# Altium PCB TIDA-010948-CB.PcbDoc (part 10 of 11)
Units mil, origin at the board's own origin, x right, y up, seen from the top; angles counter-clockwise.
Board outline 8100 x 8400 mil, 8 copper layers (L01 - TOP, L02 - GND, L03 - SIG, L04 - GND, L05 - PWR, L06 - SIG, L07 - GND, L08 - BOTTOM), stack 59.656 mil thick; 711 components, 572 nets, 2646 pads, 1325 vias.
Unrouted connection lines stored in the file: 988.
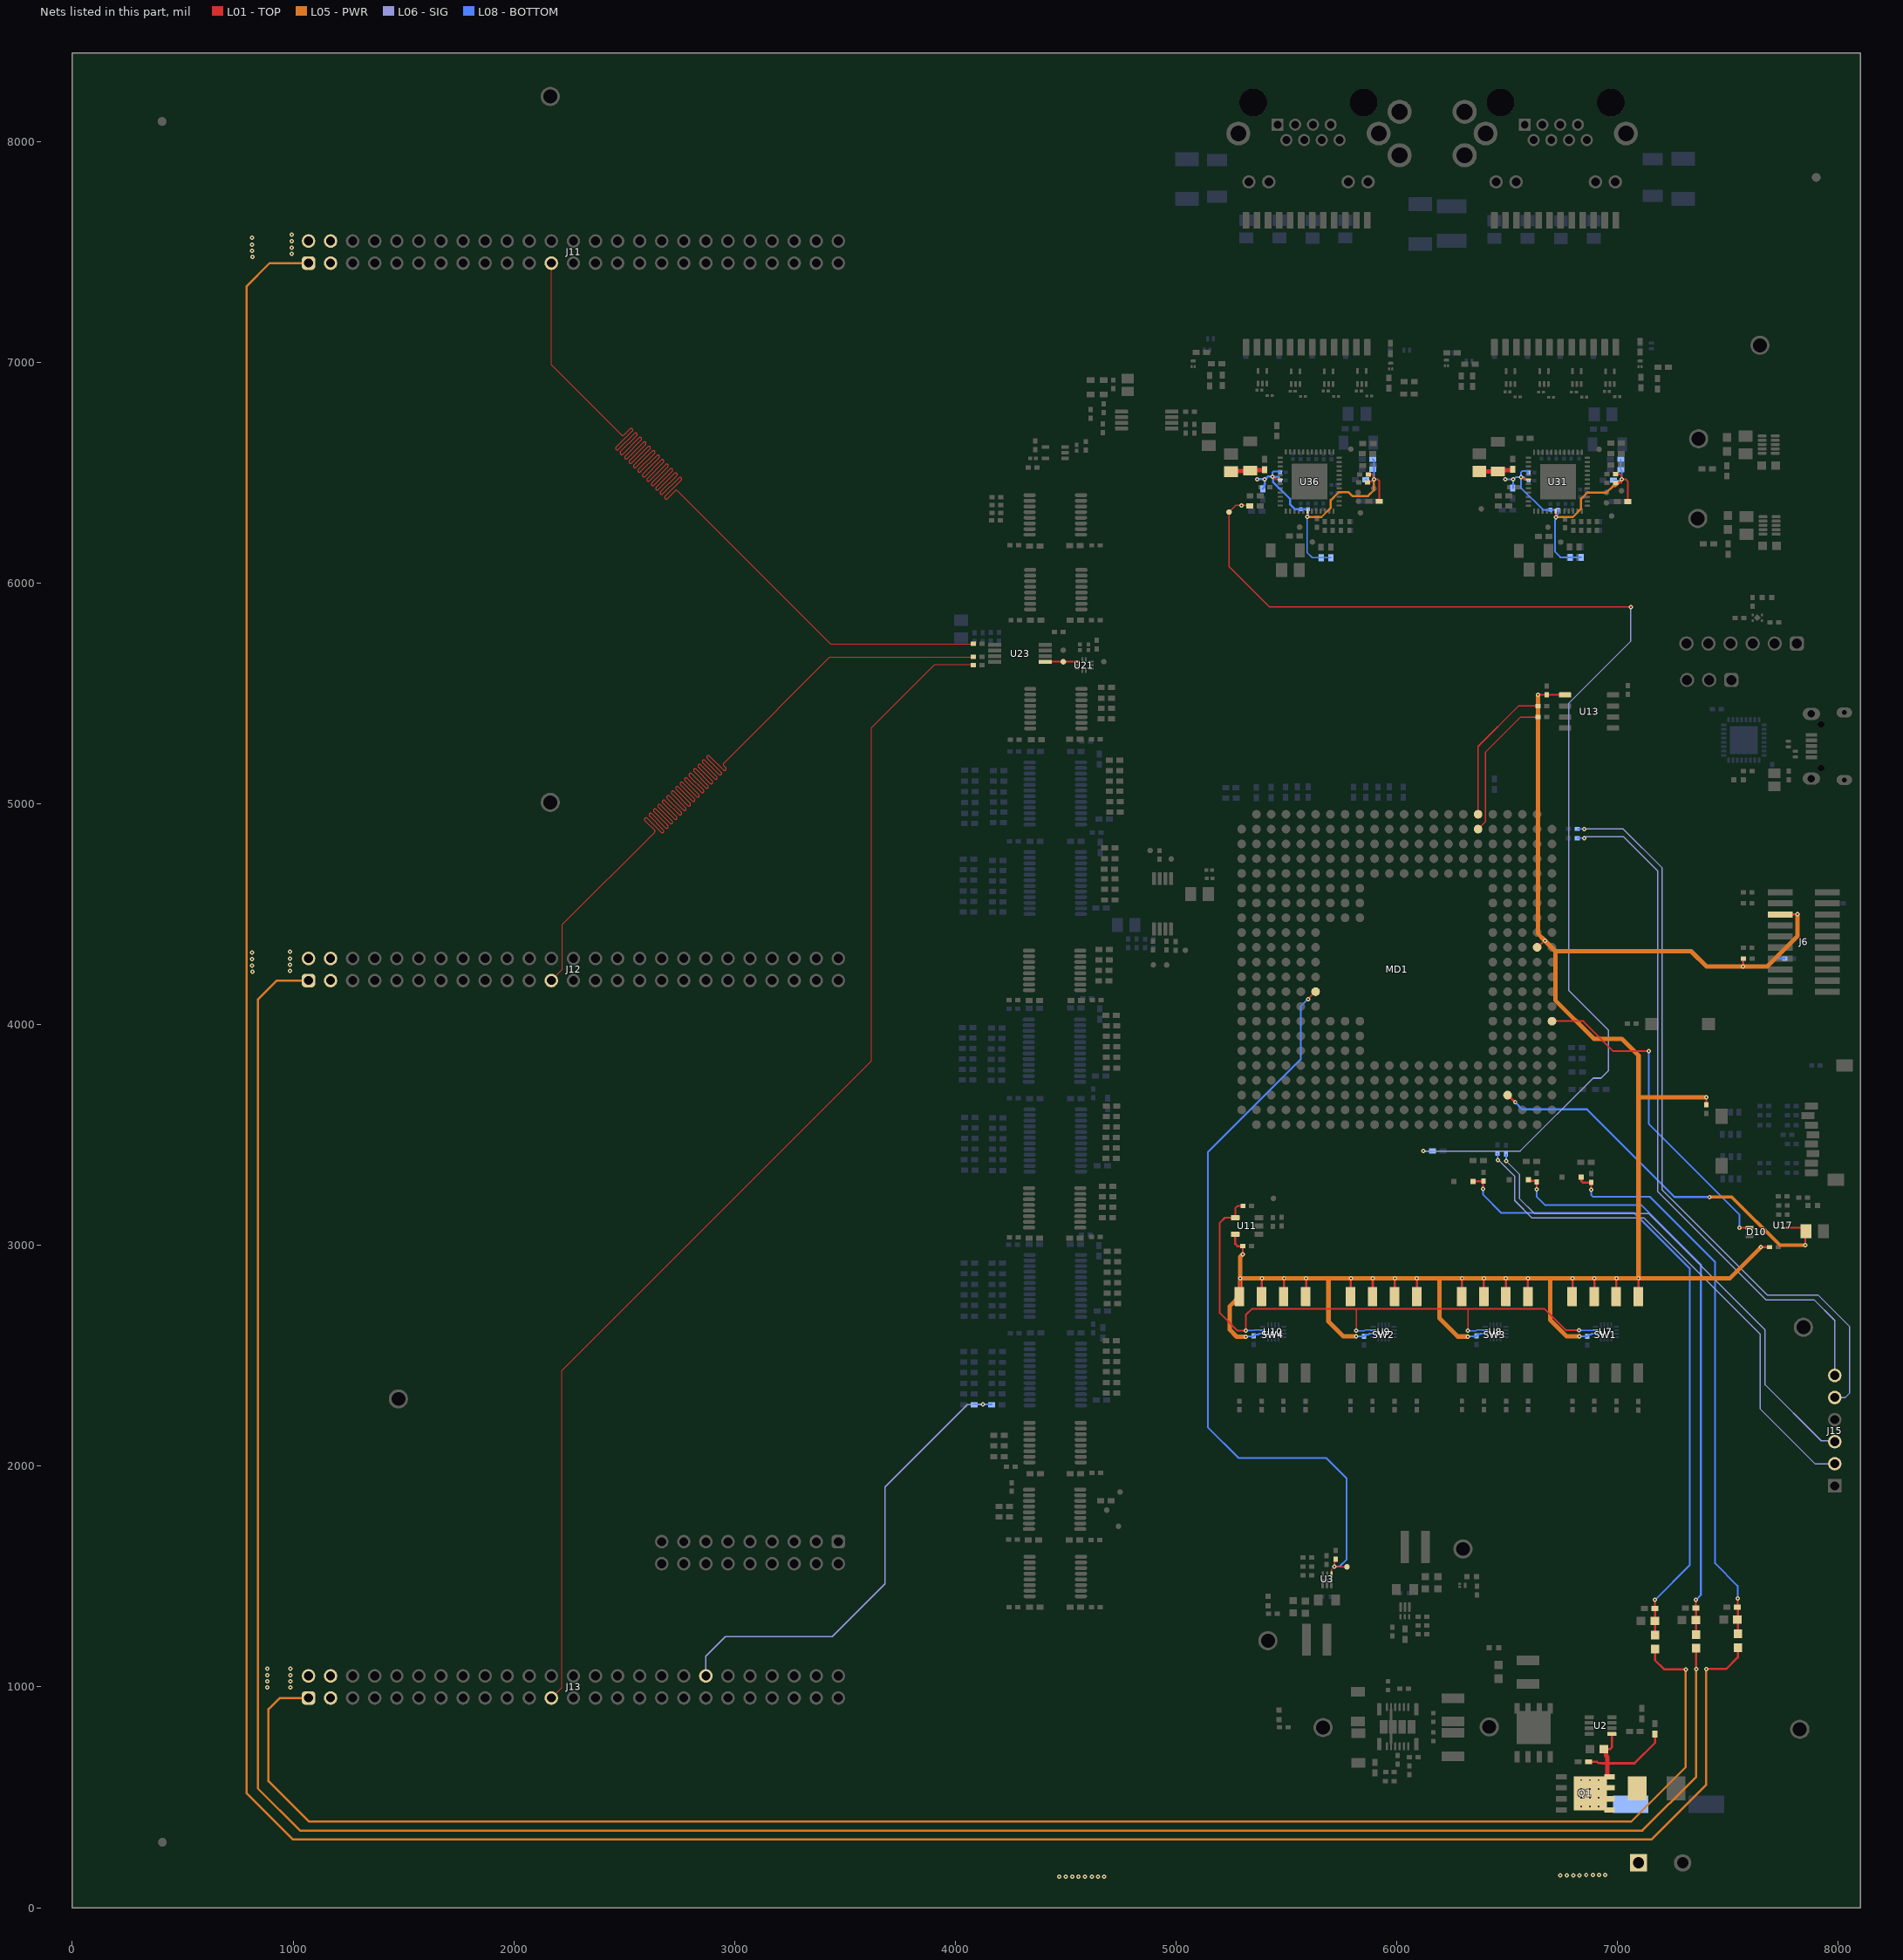
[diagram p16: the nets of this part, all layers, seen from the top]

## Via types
v1: diameter 19.68, hole 7.87, L01 - TOP to L08 - BOTTOM, 1310 vias
v2: diameter 20, hole 7.87, L01 - TOP to L08 - BOTTOM, tented both sides, 7 vias
v3: diameter 200, hole 144, L01 - TOP to L08 - BOTTOM, 6 vias
v4: diameter 20, hole 8, L01 - TOP to L08 - BOTTOM, tented both sides, 2 vias

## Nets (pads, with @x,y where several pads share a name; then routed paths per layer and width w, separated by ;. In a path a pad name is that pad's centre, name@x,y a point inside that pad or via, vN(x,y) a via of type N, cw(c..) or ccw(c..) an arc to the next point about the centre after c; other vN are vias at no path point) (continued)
PWMC6L: C102.1 J13.38 R206.2 | length 2154.7
  L06 - SIG w5.25: J13.38@2870,1050 2870,1140 2957.75,1227.75 3442.25,1227.75 3680.5,1466 3680.5,1905.36 4054.64,2279.5 v1(4125.5,2279.5)
  L08 - BOTTOM w8: C102.1@4084.78,2279.5 v1(4125.5,2279.5) 4126,2279 R206.2@4164.38,2279
RESETSTATz: D10.1 MD1.R22 | length 1511.6
  L01 - TOP w8: MD1.R22@6702.76,4015.35 6844.15,4015.35 6979,3880.5 v1(7141,3880.5) ; v1(7552,3080) 7552.34,3080.34 7598.16,3080.34 D10.1@7598.5,3080.69
  L08 - BOTTOM w8: v1(7141,3880.5) 7141,3551 7552,3140 v1(7552,3080)
SBC1: J15.2 R310.2 | length 2391.2
  L06 - SIG w6: v1(6457,3385.5) 6461.5,3385.5 6534,3313 6534,3203 6613.21,3123.79 7120.5,3123.79 7645.5,2598.79 7645.5,2260 7894.5,2011 J15.2@7984,2011
  L08 - BOTTOM w6: R310.2@6455.5,3416.81 6457,3415.31 v1(6457,3385.5)
SBC2: J15.6 R307.1 | length 3172.9
  L06 - SIG w6: v1@6848.5,4850.5 7027,4850.5 7181,4696.5 7181,3244.5 7672,2753.5 7890.5,2753.5 7984,2660 J15.6@7984,2411
  L08 - BOTTOM w6: R307.1@6818.19,4844 6818.69,4844.5 v1(6848.5,4844.5)
SDM_CLK_AX12: J11.23 R111.2 | length 5579
  L01 - TOP w4.25: J11.23@2170,7449.2 2170,6989 2474,6685 2488.69,6670.31 ccw(c2493.73,6675.35) 2498.76,6670.31 2526.59,6698.14 cw(c2531.62,6693.1) 2536.66,6698.14 cw(c2531.62,6693.1) 2536.66,6688.06 2463.17,6614.57 ccw(c2468.21,6609.53) 2463.17,6604.49 ccw(c2468.21,6609.53) 2473.25,6604.49 2546.74,6677.98 cw(c2551.78,6672.95) 2556.82,6677.98 cw(c2551.78,6672.95) 2556.82,6667.91 2483.32,6594.42 ccw(c2488.36,6589.38) 2483.32,6584.34 ccw(c2488.36,6589.38) 2493.4,6584.34 2566.89,6657.83 cw(c2571.93,6652.79) 2576.97,6657.83 cw(c2571.93,6652.79) 2576.97,6647.75 2503.48,6574.26 ccw(c2508.52,6569.23) 2503.48,6564.19 ccw(c2508.52,6569.23) 2513.55,6564.19 2587.04,6637.68 cw(c2592.08,6632.64) 2597.12,6637.68 cw(c2592.08,6632.64) 2597.12,6627.6 2523.63,6554.11 ccw(c2528.67,6549.07) 2523.63,6544.04 ccw(c2528.67,6549.07) 2533.71,6544.04 2607.2,6617.53 cw(c2612.23,6612.49) 2617.27,6617.53 cw(c2612.23,6612.49) 2617.27,6607.45 2543.78,6533.96 ccw(c2548.82,6528.92) 2543.78,6523.88 ccw(c2548.82,6528.92) 2553.86,6523.88 2627.35,6597.37 cw(c2632.39,6592.33) 2637.43,6597.37 cw(c2632.39,6592.34) 2637.43,6587.3 2563.93,6513.81 ccw(c2568.97,6508.77) 2563.93,6503.73 ccw(c2568.97,6508.77) 2574.01,6503.73 2647.5,6577.22 cw(c2652.54,6572.18) 2657.58,6577.22 cw(c2652.54,6572.18) 2657.58,6567.14 2584.09,6493.65 ccw(c2589.13,6488.62) 2584.09,6483.58 ccw(c2589.13,6488.62) 2594.16,6483.58 2667.65,6557.07 cw(c2672.69,6552.03) 2677.73,6557.07 cw(c2672.69,6552.03) 2677.73,6546.99 2604.24,6473.5 ccw(c2609.28,6468.46) 2604.24,6463.42 ccw(c2609.28,6468.46) 2614.32,6463.42 2687.81,6536.92 cw(c2692.84,6531.88) 2697.88,6536.92 cw(c2692.84,6531.88) 2697.88,6526.84 2624.39,6453.35 ccw(c2629.43,6448.31) 2624.39,6443.27 ccw(c2629.43,6448.31) 2634.47,6443.27 2707.96,6516.76 cw(c2713,6511.72) 2718.04,6516.76 cw(c2713,6511.72) 2718.04,6506.69 2644.54,6433.2 ccw(c2649.58,6428.16) 2644.54,6423.12 ccw(c2649.58,6428.16) 2654.62,6423.12 2728.11,6496.61 cw(c2733.15,6491.57) 2738.19,6496.61 cw(c2733.15,6491.57) 2738.19,6486.53 2664.7,6413.04 ccw(c2669.74,6408.01) 2664.7,6402.97 ccw(c2669.74,6408.01) 2674.77,6402.97 2748.26,6476.46 cw(c2753.3,6471.42) 2758.34,6476.46 cw(c2753.3,6471.42) 2758.34,6466.38 2684.85,6392.89 ccw(c2689.89,6387.85) 2684.85,6382.81 ccw(c2689.89,6387.85) 2694.93,6382.81 2730.52,6418.41 cw(c2735.56,6413.37) 2740.59,6418.41 2742.1,6416.9 3434,5725 R111.2@4081.81,5725
SDM_CLK_AX34: J12.23 R112.2 | length 5578.3
  L01 - TOP w4.25: J12.23@2170,4199.6 2220,4249.6 2220,4453.59 2635.92,4869.5 2637.42,4871.01 ccw(c2632.38,4876.05) 2637.42,4881.08 2593.78,4924.72 cw(c2598.82,4929.76) 2593.78,4934.8 cw(c2598.82,4929.76) 2603.86,4934.8 2667.53,4871.13 ccw(c2672.57,4876.16) 2677.61,4871.13 ccw(c2672.57,4876.16) 2677.61,4881.2 2613.94,4944.87 cw(c2618.97,4949.91) 2613.94,4954.95 cw(c2618.97,4949.91) 2624.01,4954.95 2687.68,4891.28 ccw(c2692.72,4896.32) 2697.76,4891.28 ccw(c2692.72,4896.32) 2697.76,4901.35 2634.09,4965.03 cw(c2639.13,4970.06) 2634.09,4975.1 cw(c2639.13,4970.06) 2644.16,4975.1 2707.84,4911.43 ccw(c2712.87,4916.47) 2717.91,4911.43 ccw(c2712.87,4916.47) 2717.91,4921.51 2654.24,4985.18 cw(c2659.28,4990.22) 2654.24,4995.25 cw(c2659.28,4990.22) 2664.32,4995.25 2727.99,4931.58 ccw(c2733.03,4936.62) 2738.06,4931.58 ccw(c2733.03,4936.62) 2738.06,4941.66 2674.39,5005.33 cw(c2679.43,5010.37) 2674.39,5015.41 cw(c2679.43,5010.37) 2684.47,5015.41 2748.14,4951.74 ccw(c2753.18,4956.77) 2758.22,4951.74 ccw(c2753.18,4956.77) 2758.22,4961.81 2694.55,5025.48 cw(c2699.58,5030.52) 2694.55,5035.56 cw(c2699.58,5030.52) 2704.62,5035.56 2768.29,4971.89 ccw(c2773.33,4976.93) 2778.37,4971.89 ccw(c2773.33,4976.93) 2778.37,4981.96 2714.7,5045.64 cw(c2719.74,5050.67) 2714.7,5055.71 cw(c2719.74,5050.67) 2724.77,5055.71 2788.45,4992.04 ccw(c2793.48,4997.08) 2798.52,4992.04 ccw(c2793.48,4997.08) 2798.52,5002.12 2734.85,5065.79 cw(c2739.89,5070.83) 2734.85,5075.86 cw(c2739.89,5070.83) 2744.93,5075.86 2808.6,5012.19 ccw(c2813.64,5017.23) 2818.67,5012.19 ccw(c2813.64,5017.23) 2818.67,5022.27 2755,5085.94 cw(c2760.04,5090.98) 2755,5096.02 cw(c2760.04,5090.98) 2765.08,5096.02 2828.75,5032.35 ccw(c2833.79,5037.38) 2838.83,5032.35 ccw(c2833.79,5037.38) 2838.83,5042.42 2775.16,5106.09 cw(c2780.19,5111.13) 2775.16,5116.17 cw(c2780.19,5111.13) 2785.23,5116.17 2848.9,5052.5 ccw(c2853.94,5057.54) 2858.98,5052.5 ccw(c2853.94,5057.54) 2858.98,5062.57 2795.31,5126.25 cw(c2800.35,5131.28) 2795.31,5136.32 cw(c2800.35,5131.28) 2805.38,5136.32 2869.06,5072.65 ccw(c2874.09,5077.69) 2879.13,5072.65 ccw(c2874.09,5077.69) 2879.13,5082.73 2815.46,5146.4 cw(c2820.5,5151.44) 2815.46,5156.48 cw(c2820.5,5151.44) 2825.54,5156.48 2889.21,5092.8 ccw(c2894.25,5097.84) 2899.28,5092.8 ccw(c2894.25,5097.84) 2899.28,5102.88 2835.61,5166.55 cw(c2840.65,5171.59) 2835.61,5176.63 cw(c2840.65,5171.59) 2845.69,5176.63 2909.36,5112.96 ccw(c2914.4,5117.99) 2919.44,5112.96 ccw(c2914.4,5117.99) 2919.44,5123.03 2855.77,5186.7 cw(c2860.8,5191.74) 2855.77,5196.78 cw(c2860.8,5191.74) 2865.84,5196.78 2929.51,5133.11 ccw(c2934.55,5138.15) 2939.59,5133.11 ccw(c2934.55,5138.15) 2939.59,5143.18 2875.92,5206.86 cw(c2880.96,5211.89) 2875.92,5216.93 cw(c2880.96,5211.89) 2885.99,5216.93 2949.67,5153.26 ccw(c2954.7,5158.3) 2959.74,5153.26 ccw(c2954.7,5158.3) 2959.74,5163.34 2949.78,5173.3 cw(c2954.82,5178.33) 2949.78,5183.37 2963.91,5197.5 3430.41,5664 4080.81,5664 R112.2@4082.31,5665.5
SDM_CLK_AX56: J13.23 R110.2 | length 5576.2
  L01 - TOP w4.25: J13.23@2170,950 2217.5,997.5 2217.5,2433 3621,3836.5 3621,5345.5 3906,5630.5 4079.81,5630.5 R110.2@4081.81,5628.5
SDM_CLK_SOURCE: TP23.1 U21.8 U23.1 | length 144.3
  L01 - TOP w6: U23.1@4407.17,5643.11 U23.1@4407.41,5643.35 ; TP23.1@4488.77,5643.35 TP23.1@4489,5643.58 TP23.1@4489.15,5643.73 ; U21.8@4551,5643.73 U21.8@4551.15,5643.88
  L01 - TOP w8: U23.1@4407.41,5643.35 TP23.1@4488.77,5643.35 ; TP23.1@4489.15,5643.73 U21.8@4551,5643.73
STO1: J15.3 R309.2 | length 2256.4
  L06 - SIG w6: v1(6495.5,3382) 6555,3322.5 6555,3212.5 6623.5,3144 7141,3144 7668.5,2616.5 7668.5,2368.5 7922.5,2114.5 7980.5,2114.5 J15.3@7984,2111
  L08 - BOTTOM w6: R309.2@6494.5,3413.31 6495.5,3412.31 v1(6495.5,3382)
STO2: J15.5 R306.1 | length 3398.1
  L06 - SIG w6: v1(6848.5,4886) 7026,4886 7202.5,4709.5 7202.5,3250.5 7677.5,2775.5 7908,2775.5 8050.5,2633 8050.5,2329.5 8032,2311 J15.5@7984,2311
  L08 - BOTTOM w6: R306.1@6818.19,4886.5 6818.69,4886 v1(6848.5,4886)
Switch_Bootcfg: R60.2 U7.15 U8.15 U9.15 U10.15 U11.4 | length 2864.9
  L01 - TOP w6: v1(5816,2613) 5816,2713 ; v1(6322,2613) 6322,2713
  L01 - TOP w8: R60.2@5303.31,3179 5279,3179 5267.87,3167.87 U11.4@5267.87,3125.4 5221.4,3125.4 5198,3102 5198,2693 5277.22,2613.78 v1(5316,2613.78) 5316,2685 5344,2713 5816,2713 6322,2713 6669,2713 6767,2615 v1(6825,2615)
  L08 - BOTTOM w6: v1(5316,2613.78) 5352.55,2613.78 5354.65,2615.87 U10.15@5392.76,2615.87 ; v1(5816,2613) 5852.66,2613 5855.54,2615.87 U9.15@5893.76,2615.87 ; v1(6322,2613) 6358.66,2613 6361.54,2615.87 U8.15@6399.76,2615.87 ; v1(6825,2615) 6825.44,2615.44 6899.32,2615.44 U7.15@6899.76,2615.87
SYSCLKOUT0: R220.1 R260.1 TP13.1 | length 5574.7
  L01 - TOP w6: R260.1@5333.88,6349 5331.38,6351.5 v1(5295.5,6351.5) 5270,6351.5 TP13.1@5240,6321.5 5240,6074.5 5422.56,5891.94 v1(7060,5891.94)
  L06 - SIG w6: v1(6120,3427.5) 6559.15,3427.5 6889.15,3757.5 6925,3757.5 6959.5,3792 6959.5,3974 6778.32,4155.18 6778.32,5454.81 7060,5736.49 v1(7060,5891.94) v1@7060,5893
  L08 - BOTTOM w6: v1(6120,3427.5) 6160.88,3427.5 R220.1@6161.38,3427
TQMaX4XxL_PGOOD: MD1.N6 R19.2 TP22.1 U3.1 | length 3465.8
  L01 - TOP w6: U3.1@5703.69,1511.59 5703.69,1530.68 v1(5718,1545) ; R19.2@5723,1578.31 5718,1573.31 v1(5718,1545) ; TP22.1@5774,1544 5773.5,1544.5 5718.5,1544.5 v1(5718,1545)
  L01 - TOP w8: v1(5598,4116) 5598.34,4116 5631.55,4149.21 MD1.N6@5631.89,4149.21
  L08 - BOTTOM w8: v1(5598,4116) 5565.78,4083.78 5565.78,3844.28 5145,3423.5 5145,3388.65 5145,2175 5283,2037 5680,2037 5773,1944 5773,1578 5740,1545 v1(5718,1545)
UART0_RXD: MD1.A17 R61.1 | length 655.7
  L01 - TOP w6: MD1.A17@6368.11,4952.36 6368.11,5260.11 6551,5443 R61.1@6640.31,5443
UART0_TXD: MD1.B17 R63.1 | length 666.8
  L01 - TOP w6: MD1.B17@6368.11,4885.43 6401,4918.32 6401,5233 6561,5393 R63.1@6640.31,5393
V_1V8_MOD: C28.1 C30.1 C31.1 C32.1 C33.1 C35.1 J6.5 MD1.K21 R82.2 R86.2 R87.2 R88.2 SW1.5 SW1.6 SW1.7 SW1.8 SW2.5 SW2.6 SW2.7 SW2.8 SW3.5 SW3.6 SW3.7 SW3.8 SW4.5 SW4.6 SW4.7 SW4.8 U7.14 U8.14 U9.14 U10.14 U11.5 U13.1 | length 10728.1
  L01 - TOP w8: v1(5301.5,2959.5) 5301.91,2959.91 5301.91,2995.59 C28.1@5302.31,2996 ; v1(6639,5493) 6639.66,5493.66 6679.34,5493.66 C35.1@6680,5494.31 6680.66,5493.66 6762.07,5493.66 U13.1@6762.73,5493 ; R82.2@7402.83,3636.51 7402.91,3636.6 7402.91,3670.41 v1(7403,3670.5) ; v1(7650,2992) R88.2@7688.31,2992
  L01 - TOP w10: U11.5@5267.87,3050.6 5267.87,3006.13 5278,2996 C28.1@5302.31,2996 ; SW4.8@5287,2769.23 5290,2772.23 v1(5290,2850) v1@5290,2851 ; SW4.7@5387,2769.23 5389,2771.23 v1(5389,2850) ; SW4.6@5487,2769.23 5489,2771.23 v1(5489,2850) ; SW4.5@5587,2769.23 5589,2771.23 v1(5589,2850) ; SW2.8@5790,2769.23 5792,2771.23 v1(5792,2850) ; SW2.7@5890,2769.23 5891,2770.23 v1(5891,2850) ; SW2.6@5990,2769.23 5991,2770.23 v1(5991,2850) ; SW2.5@6090,2769.23 6091,2770.23 v1(6091,2850) ; SW3.8@6294,2769.23 6295,2770.23 v1(6295,2850) ; SW3.7@6394,2769.23 v1(6394,2850) ; SW3.6@6494,2769.23 v1(6494,2850) ; SW3.5@6594,2769.23 v1(6594,2850) ; MD1.K21@6635.83,4349.99 6638.41,4349.99 6668.42,4380 v1(6671,4380) ; SW1.8@6794,2768.23 6796,2770.23 v1(6796,2850) ; SW1.7@6894,2768.23 6895,2769.23 v1(6895,2850) ; SW1.6@6994,2768.23 6995,2769.23 v1(6995,2850) ; SW1.5@7094,2768.23 7095,2769.23 v1(7095,2850) ; v1(7569,4263) 7569.66,4263.66 7569.66,4298.34 R86.2@7570.31,4299 ; J6.5@7737.5,4499 7738,4499.5 7814.5,4499.5 v1(7815,4500)
  L05 - PWR w8: 7095,3670.73 7097.27,3673
  L05 - PWR w20: v1(5301.5,2959.5) 5290,2948 v1(5290,2850) ; v1(5316,2586) 5275,2586 5243.62,2617.38 5243.62,2725 5290,2771.38 v1(5290,2850) ; v1(5816,2588) 5757.42,2588 5690.5,2654.92 5690.5,2850 ; v1(6322,2587) 6276.48,2587 6193,2670.48 6193,2850 ; v1(6639,5493) 6639,4412 v1(6671,4380) 6718.5,4332.5 7333.5,4332.5 7403,4263 v1(7569,4263) 7678,4263 7815,4400 v1(7815,4500) ; 6718.24,4332.76 6718.24,4110.26 6893.1,3935.4 7019.6,3935.4 7095,3860 7095,3670.73 ; v1(6828,2588) 6769.5,2588 6695,2662.5 6695,2850 ; v1(7403,3670.5) 7402.77,3670.73 7095,3670.73 ; v1(7650,2992) 7508,2850 v1(7095,2850) ; v1(5290,2850) v1(5389,2850) v1(5489,2850) v1(5589,2850) 5690.5,2850 ; 5690.5,2850 v1(5792,2850) v1(5891,2850) v1(5991,2850) v1(6091,2850) 6193,2850 ; 6193,2850 v1(6295,2850) v1(6394,2850) v1(6494,2850) v1(6594,2850) 6695,2850 ; 6695,2850 v1(6796,2850) v1(6895,2850) v1(6995,2850) v1(7095,2850) ; v1(7095,2850) 7095,3670.73
  L08 - BOTTOM w8: v1(5316,2586) 5317.84,2587.84 5350.16,2587.84 C33.1@5352,2589.68 5352,2590.16 5357.84,2596 5373,2596 5377.06,2600.06 5392.69,2600.06 U10.14@5392.76,2600.13 ; v1(5816,2588) 5816.16,2587.84 5851.84,2587.84 C32.1@5852,2587.68 5852,2589.65 5857.84,2595.5 5872.5,2595.5 5877.06,2600.06 5893.69,2600.06 U9.14@5893.76,2600.13 ; v1(6322,2587) 6323.84,2588.84 6360.16,2588.84 C31.1@6362,2590.68 6362,2592.16 6367.84,2598 6378,2598 6380.13,2600.13 U8.14@6399.76,2600.13 ; v1(6828,2588) 6828.16,2587.84 6861.84,2587.84 C30.1@6862,2587.68 ; C30.1@6862,2589.65 6867.84,2595.5 6879.5,2595.5 6884.06,2600.06 6899.69,2600.06 U7.14@6899.76,2600.13
  L08 - BOTTOM w10: v1(7569,4263) 7681,4263 7717,4299 R87.2@7757.31,4299
V_VDDSHV5_SD: C46.1 MD1.Y19 U17.A2 U17.B2 | length 1805.8
  L01 - TOP w8: U17.B2@7749,3080.16 U17.A2@7768.69,3080.16 7836.84,3080.16 C46.1@7853,3064 7851,3062 v1(7851,3000.5)
  L01 - TOP w10: MD1.Y19@6501.97,3680.7 6502.63,3680.7 6535.34,3648 v1(6536,3648)
  L05 - PWR w15: v1(7417,3219) 7517.28,3219 7735.78,3000.5 v1(7851,3000.5)
  L08 - BOTTOM w10: v1(6536,3648) 6568,3616 6862,3616 7259,3219 v1(7417,3219)
VBUS: C3.1 C11.1 D3.2 J1.1 J11.1 J11.2 J11.3 J11.4 J12.1 J12.2 J12.3 J12.4 J13.1 J13.2 J13.3 J13.4 Q1.5 Q1.6 Q1.7 Q1.8 Q1.9 R9.2 R11.2 R311.2 R312.2 R313.2 U2.5 | length 34201.3
  L01 - TOP w10: R9.2@6868.62,661 6906.62,661 6913.43,654.19 6926.81,654.19 6927,654 6954,654 7077,654 7170,747 R11.2@7170,786.38 ; C11.1@6937.5,719 6938.48,719 6967.02,719 6974.18,726.16 U2.5@6974.18,786.61 ; R311.2@7169.86,1171.41 7169.86,1121.14 7212,1079 v1(7308.5,1079) ; R312.2@7355.17,1174.69 7356.55,1173.31 v1(7356.55,1081.61) ; v1(7401.5,1081) 7492,1081 7544.62,1133.62 R313.2@7544.62,1178.24
  L01 - TOP w20: C11.1@6938.48,719 6947.18,710.3 6947.18,688.82 6954,682 6954,654 6954,595 6956,593 Q1.8@6964,593
  L05 - PWR w10: J13.1@1070,950 940,950 889,899 889,573 1072,390 7061.5,390 7308.5,637 v1(7308.5,1079) ; J12.1@1070,4199.6 926.1,4199.6 840,4113.5 840,540.5 1031.5,349 7112,349 7356.55,593.55 v1(7356.55,1081.61) ; J11.1@1070,7449.2 894.2,7449.2 788.5,7343.5 788.5,519 999,308.5 7152.5,308.5 7401.5,557.5 v1(7401.5,1081)
  other v1: 4471,139.5 4501,139.5 4529,139.5 4557,140 4588,140.5 4618,140.5 4646,140.5 4674,141 6741,146.5 6771,146.5 6799,146.5 6827,147 6858,147.5 6888,147.5 6916,147.5 6944,148 6834.5,458 6874.5,458 6914.5,458 6834.5,498 6874.5,498 6914.5,498 6834.5,538 6874.5,538 6914.5,538 6834.5,578 6874.5,578 6914.5,578 883.5,997 987.5,997.5 883,1025 987,1025.5 883,1053 987,1053.5 883,1083 987,1083.5 815.5,4240 986.5,4243.5 815,4268 986,4271.5 815,4296 986,4299.5 815,4326 986,4329.5 815.5,7477.5 993.5,7491.5 815,7505.5 993,7519.5 815,7533.5 993,7547.5 815,7563.5 993,7577.5
VCC_ETH1: C109.1 C110.1 C111.1 C121.1 C124.1 C125.1 L6.1 R213.2 R214.2 R215.2 R216.2 R217.2 R218.2 R219.2 R242.1 R243.1 U31.18 U31.30 | length 1754.9
  L01 - TOP w8: v1(6562.36,6480.28) 6565.52,6480.28 6576.23,6469.57 6595.42,6469.57 U31.18@6596.14,6468.84 ; U31.30@6720.16,6325.14 6720.26,6325.04 6720.26,6298.63 v1(6720.36,6298.53) ; R243.1@6990.87,6453.13 7015.05,6453.13 7017.5,6455.58 7017.5,6467.41 v1(7019.74,6469.65) ; R242.1@6991.34,6494.19 7010.86,6494.19 7017.5,6487.55 7017.5,6471.88 v1(7019.74,6469.65) ; R215.2@7046.12,6368.5 7046.12,6456.88 7046.12,6460.67 7037.15,6469.65 v1(7019.74,6469.65)
  L01 - TOP w20: L6.1@6373.86,6504.03 6375.89,6506.06 6458.32,6506.06 6463.01,6510.75 6524.05,6510.75 6525.86,6512.56 C121.1@6525.86,6513.41
  L05 - PWR w10: v1(6720.36,6298.53) 6796.78,6298.53 6835.18,6336.92 6835.18,6380.98 6863.92,6409.72 6949.84,6409.72 6978.88,6438.76 6988.85,6438.76 v1(7019.74,6469.65)
  L08 - BOTTOM w6: R218.2@6981.95,6464.94 v1@7011.88,6464.94 ; R216.2@7014.63,6560.55 7014.74,6560.44 R217.2@7014.74,6513.53 7019.74,6508.53 v1(7019.74,6469.65)
  L08 - BOTTOM w8: v1(6491.86,6470.03) v1(6526.86,6470.03) ; R219.2@6526,6430.12 6526.43,6430.55 6526.43,6469.6 v1(6526.86,6470.03) ; C110.1@6593.9,6497.89 6593.9,6502.32 6591.45,6504.77 6587.02,6504.77 6585.29,6506.5 6567.81,6506.5 6563.12,6501.81 6563.12,6481.04 v1(6562.36,6480.28) ; C124.1@6596.51,6463.5 6592.24,6467.77 6581.77,6467.77 6579.97,6469.57 6579.97,6474.84 6575.29,6479.53 6563.11,6479.53 v1(6562.36,6480.28) ; R214.2@6834.79,6116.94 6741.06,6116.94 6717.02,6140.98 6717.02,6284.83 6718.12,6285.94 6718.12,6296.29 v1(6720.36,6298.53) 6720.36,6301.31 6730,6310.95 C111.1@6730,6332.01 C125.1@6696,6332.01 6661.99,6332.01 6562.36,6431.64 v1(6562.36,6480.28) ; v1(6526.86,6470.03) 6530.02,6470.03 6540.27,6480.28 v1(6562.36,6480.28)
VCC_ETH2: C151.1 C152.1 C153.1 C163.1 C166.1 C167.1 L9.1 R253.2 R254.2 R255.2 R256.2 R257.2 R258.2 R259.2 R282.1 R283.1 U36.18 U36.30 | length 1781.4
  L01 - TOP w8: v1(5437.5,6480.75) 5440.66,6480.75 5451.37,6470.04 5470.56,6470.04 U36.18@5471.28,6469.31 ; U36.30@5595.3,6325.61 5595.4,6325.51 5595.4,6299.1 v1(5595.5,6299) ; R283.1@5868.02,6455.19 5871.83,6459 5885.92,6459 5895.92,6469 v1(5896,6469) ; R282.1@5870.46,6493.35 5887.97,6493.35 5893.76,6487.55 5893.76,6471.24 v1(5896,6469) ; R255.2@5920.62,6370 5920.62,6462.88 5914.5,6469 v1(5896,6469)
  L01 - TOP w20: L9.1@5249,6504.5 5251.04,6506.54 5333.46,6506.54 C151.1@5335.5,6508.57 5338.15,6511.22 5399.19,6511.22 5401,6513.04 C163.1@5401,6513.88
  L05 - PWR w10: v1(5595.5,6299) 5658.95,6299 5700.5,6340.55 5700.5,6375.5 5735.84,6410.84 5781.6,6410.84 5798.28,6394.16 5869.72,6394.16 5896,6420.44 v1(5896,6469)
  L08 - BOTTOM w6: v1(5595.5,6299) 5593.16,6296.66 5593.16,6139.34 5617,6115.5 5700.88,6115.5 R254.2@5702,6114.38
  L08 - BOTTOM w8: v1(5437.5,6480.75) 5437.5,6500.81 5442.19,6505.5 5467.51,6505.5 C166.1@5471.51,6501.5 ; C152.1@5469.51,6467 C152.1@5471.51,6465 ; R258.2@5859.62,6467 5867.43,6459.19 5881.31,6459.19 5881.5,6459 5882.84,6459 5892.84,6469 v1(5896,6469) 5896,6555.62 R256.2@5891.62,6560
  L08 - BOTTOM w10: v1(5367,6470.5) v1(5402,6470.5) ; R259.2@5393,6426.62 5399.81,6433.43 5399.81,6443.47 5402,6445.66 v1(5402,6470.5) ; C152.1@5469.51,6467 5468.72,6467 5467.45,6468.27 5467.45,6476.95 5463.65,6480.75 v1@5437.5,6480.75 ; v1(5595.5,6299) 5596.75,6300.25 5596.75,6332.76 C153.1@5598,6334.01 C167.1@5565.5,6334.01 5539.99,6334.01 5515.99,6358.01 5515.99,6382.01 5439.35,6458.65 5439.35,6478.9 v1@5437.5,6480.75 ; v1(5402,6470.5) 5404.62,6470.5 5417.12,6483 5423,6483 5423.4,6482.6 5435.65,6482.6 v1(5437.5,6480.75)
VSENSE_AX12: C177.2 D20.2 R73.1 R311.1 R314.2 | length 2908.4
  L01 - TOP w8: v1(6391,3256.5) 6391.5,3257 6391.5,3290 R73.1@6391.34,3290.16 ; C177.2@7168.48,1355.4 7169.5,1356.42 v1(7169.5,1394.5)
  L01 - TOP w10: D20.2@6345.81,3289.5 6346.46,3290.16 R73.1@6391.34,3290.16 ; C177.2@7168.48,1355.4 7169.86,1354.03 R311.1@7169.86,1234.4
  L08 - BOTTOM w8: v1(6391,3256.5) 6391,3229.5 6473.5,3147 7075.5,3147 7327,2895.5 7327,1552 v1(7169.5,1394.5)
VSENSE_AX34: C205.2 D21.2 R75.1 R312.1 R315.2 | length 2663.9
  L01 - TOP w8: v1(6633.5,3254) 6633.56,3254.06 R75.1@6633.63,3287.63 R75.1@6633.63,3287.63 ; C205.2@7355.17,1355.95 7355.5,1356.28 v1(7355.5,1394.5)
  L01 - TOP w10: D21.2@6596.81,3298 6602.79,3292.01 6629.24,3292.01 R75.1@6633.63,3287.63 ; R312.1@7355.17,1237.69 C205.2@7355.17,1355.95
  L08 - BOTTOM w8: v1(6633.5,3254) 6633.5,3221 6672.5,3182 7108.5,3182 7377.5,2913 7377.5,1416.5 v1(7355.5,1394.5)
VSENSE_AX56: C206.2 D22.2 R77.1 R313.1 R316.2 | length 2536.8
  L01 - TOP w8: v1(6881,3252.5) R77.1@6881,3284.81 ; C206.2@7542,1362.05 7544,1364.05 v1(7544,1400.5)
  L01 - TOP w10: D22.2@6835.31,3308.5 6836.5,3307.31 6836.5,3290.23 6842.36,3284.37 6852.04,3284.37 6852.49,3284.81 R77.1@6881,3284.81 ; C206.2@7542,1362.05 7544.62,1359.43 R313.1@7544.62,1241.23
  L08 - BOTTOM w8: v1(6881,3252.5) 6881,3228 6888,3221 7145.5,3221 7442.5,2924 7442.5,1559 7544,1457.5 v1(7544,1400.5)
pads on no net: D6.1S D6.2S D7.1S D7.2S D12.1S D12.2S D13.1S D13.2S D14.1S D14.2S D15.1S D15.2S D16.1S D16.2S D17.1S D17.2S D18.1S D18.2S D19.1S D19.2S FID1.1 FID2.1 FID3.1 FID4.1 FID5.1 FID6.1 J2. J2.4 J3.2 J3.6 J6.6 J6.8 J6.17 J6.18 J6.19 J7. J9. J11.35 J11.37 J11.39 J11.41 J12.35 J12.37 J12.39 J12.41 J13.35 J13.37 J13.39 J13.41 LBL1.0 MD1.A6 MD1.A9 MD1.A12 MD1.A18 MD1.A20 MD1.A21 MD1.AA1 MD1.AA3 MD1.AA4 MD1.AA20 MD1.AA22 MD1.AB2 MD1.AB3 MD1.AB21 MD1.B20 MD1.B22 MD1.C18 MD1.C19 MD1.C21 MD1.C22 MD1.D3 MD1.D6 MD1.D12 MD1.D18 MD1.D20 MD1.D21 MD1.E6 MD1.E12 MD1.E20 MD1.E22 MD1.F1 MD1.F2 MD1.F8 MD1.F18 MD1.F19 MD1.F21 MD1.F22 MD1.G2 MD1.G5 MD1.G6 MD1.G8 MD1.G9 MD1.G18 MD1.G20 MD1.G21 MD1.H6 MD1.H7 MD1.H19 MD1.H20 MD1.H22 MD1.J1 MD1.J4 MD1.J19 MD1.J21 MD1.J22 MD1.L5 MD1.L19 MD1.L22 MD1.M1 MD1.M5 MD1.M19 MD1.M20 MD1.M22 MD1.N3 MD1.N20 MD1.N21 MD1.P4 MD1.P19 MD1.P21 MD1.P22 MD1.R1 MD1.R6 MD1.R7 MD1.R19 MD1.R20 MD1.T6 MD1.T8 MD1.T9 MD1.U4 MD1.U18 MD1.V1 MD1.V3 MD1.V12 MD1.V13 MD1.V14 MD1.V16 MD1.V20 MD1.V22 MD1.W2 MD1.W3 MD1.W14 MD1.W17 MD1.W20 MD1.Y1 MD1.Y2 MD1.Y4 MD1.Y18 MD1.Y21 MD1.Y22 Q3.0 Q4.0 Q5.0 Q6.0 Q7.0 U1.2 U1.7 U1.13 U1.15 U2.3 U3.4@5664.31,1465.33 U3.5@5684,1465.33 U3.6@5703.69,1465.33 U4.4 U5.4 U6.4@6056.69,1364.67 U6.5@6037,1364.67 U6.6@6017.31,1364.67 U12.3 U12.5 U12.6 U12.7 U12.8 U12.9 U12.10 U12.11 U12.12 U12.13 U12.21 U12.22 U12.23 U12.25 U12.27 U12.28 U12.29 U12.31 U12.32 U16.3 U21.9 U22.5 U22.7 U25.14 U25.15 U26.14 U26.15 U27.14 U27.15 U28.14 U28.15 U29.14 U29.15 U30.14 U30.15 U31.13 U31.14 U31.15 U31.16 U31.17 U31.19 U31.21 U31.23 U31.24 U31.48 U32.1 U33.1 U34.1 U35.1 U36.13 U36.14 U36.15 U36.16 U36.17 U36.19 U36.21 U36.23 U36.24 U36.48 U37.1 U38.1 U39.1 U40.1
copper on no net:
  other v3: 155,150 4050,150 7945,150 155,8250 4050,8250 7945,8250

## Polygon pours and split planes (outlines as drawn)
GND on L01 - TOP "L01_-_TOP_GND_P056" (solid, pour order 56): 632,8371.5 1278,8371.5 4715.5,8371.5 4855,8232 4855,7207 4906.5,7155.5 8028,7155.5 8080.5,7103 8080.5,6057.5 8036,6013 7335.5,6013 6939.19,5616.69 6939.19,5016.31 6979.5,4976 8043,4976 8080.5,4938.5 8080.5,52.5 8054.5,26.5 600.45,26.5 583,47.5 583,156 583,7990 583,8310.5
GND on L01 - TOP "L01_-_TOP_GND_P012" (solid, pour order 12): 5795,859 cw(c5801,859) 5801,865 5855,865 cw(c5855,854) 5866,854 ccw(c5869,854) 5869,851 6153,851 ccw(c6153,853) 6155,853 cw(c6156,853) 6156,854 6198,854 ccw(c6198,858) 6202,858 6202,863 cw(c6205,863) 6205,866 6304,866 cw(c6304,862) 6308,862 6308,773 cw(c6304,773) 6304,769 6206,769 cw(c6206,773) 6202,773 6202,780 ccw(c6199,780) 6199,783 6159,783 cw(c6159,788) 6154,788 5866,788 ccw(c5869,784) 5864,784 5864,774 cw(c5861,774) 5861,771 5801,771 cw(c5801,777) 5795,777
GND_USB on L01 - TOP "L01_-_TOP_GND_USB_P000" (solid, pour order 0): 8052,5985 7364.5,5985 6982,5602.5 6982,5024 7005,5001 8061,5001 8080,5020 8079,5021 8079,5958
NetQ1_1 on L01 - TOP "L01_-_TOP_NETQ1_1_P004" (solid, remove dead copper, pour order 4): 6654.39,710 cw(c6654.51,708.2) 6656.13,709 cw(c6620.16,701.03) 6657,700.3 6657,658.5 ccw(c6709.61,658.61) 6709.62,606 6768,606 cw(c6768,601) 6773,601 6773,486 cw(c6764,486) 6764,477 6622.51,477 cw(c6622.49,595.49) 6504,595.49 6504,654.5 cw(c6559.5,654.5) 6559.5,710
1V1 on L01 - TOP "L01_-_TOP_1V1_P023" (solid, pour order 23): 7678.61,6291.05 7678.61,6308.05 ccw(c7652.07,6308.05) 7670.83,6326.83 7670.61,6327.05 ccw(c7641.65,6298.1) 7641.64,6339.05 7369.61,6339.05 ccw(c7380.27,6270.42) 7324.19,6311.39 7320,6291.05 7320,6195.5 ccw(c7376.13,6199.91) 7339.56,6157.1 7342.61,6154.05 ccw(c7347.44,6158.88) 7347.44,6152.05 7402.11,6152.05 ccw(c7377.61,6171.38) 7408.61,6175.05 ccw(c7407.41,6175.55) 7408.61,6176.05 7408.61,6216.05 cw(c7449.53,6210.1) 7424.8,6243.24 7463.61,6282.05 cw(c7470.85,6274.82) 7470.85,6285.05 7536.54,6285.05 cw(c7536.55,6268) 7548.61,6280.05 ccw(c7558.27,6289.71) 7558.26,6276.05 7667.54,6276.05 ccw(c7667.54,6293.12) 7678.61,6280.13
VCC_ETH1 on L01 - TOP "L01_-_TOP_VCC_ETH1_P032" (solid, pour order 32): 6540.36,6530.03 6552.36,6495.03 6554.86,6495.03 6572.36,6495.03 6575.36,6492.03 6575.36,6467.03 6568.36,6460.03 6347.36,6460.03 6337.36,6470.03 6337.36,6523.53 6345.36,6530.03
VCC_ETH2 on L01 - TOP "L01_-_TOP_VCC_ETH2_P031" (solid, pour order 31): 5415.5,6530.5 5427.5,6495.5 5430,6495.5 5447.5,6495.5 5450.5,6492.5 5450.5,6467.5 5443.5,6460.5 5222.5,6460.5 5212.5,6470.5 5212.5,6524 5220.5,6530.5
2V5 on L01 - TOP "L01_-_TOP_2V5_P024" (solid, pour order 24): 7674,6653.67 7674,6670.67 ccw(c7647.46,6670.67) 7666.22,6689.45 7666,6689.67 ccw(c7637.04,6660.72) 7637.03,6701.67 7365,6701.67 ccw(c7365.6,6651.94) 7330,6686.67 7330,6674.67 cw(c7329.22,6674.34) 7330,6674.01 7330,6531.67 ccw(c7346.9,6531.67) 7334.95,6519.72 7338,6516.67 ccw(c7364.18,6539.52) 7361.82,6504.85 7393.6,6504.85 ccw(c7359.2,6533.81) 7404,6537.67 ccw(c7402.81,6538.17) 7404,6538.67 7404,6578.67 cw(c7444.92,6572.72) 7420.19,6605.86 7453,6638.67 7553.66,6638.67 7662.93,6638.67 ccw(c7662.93,6655.74) 7674,6642.74
1V8 on L01 - TOP "L01_-_TOP_1V8_P020" (solid, pour order 20): 6124.14,1482.42 cw(c6123.05,1491.87) 6114,1494.76 6114,1699.28 6119.14,1704.42 cw(c6123.96,1699.61) 6123.97,1706.42 6324.14,1706.42 cw(c6324.15,1699.22) 6329.26,1704.3 6333.14,1700.42 cw(c6257.76,1611.43) 6374,1621 cw(c6270,1597.72) 6346,1523 cw(c6330,1653.54) 6314,1523 ccw(c6306.85,1488.65) 6279,1510 6275.14,1493.42 cw(c6260.71,1493.4) 6270.9,1483.18 6270.14,1482.42 6122.14,1482.42
5V on L01 - TOP "L01_-_TOP_5V_P019" (solid, pour order 19): 5936,1340.59 cw(c5936,1350.24) 5929.17,1343.41 5927,1345.59 cw(c5931.82,1350.41) 5925,1350.41 5925,1455.59 cw(c5932.24,1455.59) 5927.12,1460.71 5930,1463.59 cw(c5932.41,1461.18) 5932.41,1464.59 6015,1464.59 6017,1462.59 cw(c6015.09,1460.38) 6018,1460.59 6018,1380.31 cw(c6008.14,1369.15) 6023,1370.07 6023,1347.83 cw(c6012.76,1347.83) 6020,1340.59
5V on L01 - TOP "L01_-_TOP_5V_P018" (solid, pour order 18): 5785,1490 cw(c5785,1480.35) 5791.83,1487.17 5794,1485 cw(c5789.18,1480.18) 5796,1480.17 5796,1375 cw(c5788.76,1375) 5793.88,1369.88 5791,1367 cw(c5788.59,1369.41) 5788.59,1366 5706,1366 5704,1368 cw(c5705.91,1370.21) 5703,1370 5703,1450.28 cw(c5712.86,1461.43) 5698,1460.52 5698,1482.76 cw(c5708.24,1482.76) 5701,1490
3V3 on L01 - TOP "L01_-_TOP_3V3_P016" (solid, pour order 16): 5597,1352 cw(c5598.09,1342.56) 5607.14,1339.66 5607.14,1147.19 cw(c5601.13,1141.17) 5607.14,1135.14 5602,1130 cw(c5597.18,1134.82) 5597.17,1128 5400,1124.5 cw(c5396,1161.72) 5372.5,1132.58 5372.5,1273.5 cw(c5392.78,1262.1) 5386.5,1284.5 5400,1293.5 cw(c5420.74,1265.62) 5425.8,1300 5440,1300 ccw(c5440,1304.83) 5443.41,1301.41 5445,1303 ccw(c5442.6,1305.41) 5446,1305.41 5446,1341 cw(c5460.49,1341) 5450.24,1351.24 5451,1352 5599,1352
5V on L01 - TOP "L01_-_TOP_5V_P014" (solid, pour order 14): 5930,873 5930,931 ccw(c5863,931) 5863,998 5586,998 ccw(c5586,959) 5547,959 5547,717 ccw(c5632.5,719) 5634.5,633.5 5901.5,633.5 ccw(c5901.5,650) 5918,650 5918,696 cw(c5931,696) 5931,709 ccw(c5931,713) 5935,713 5935,760 ccw(c5926,760) 5926,769 5900,769 ccw(c5900,743) 5874,743 5874,699 cw(c5858,699) 5858,683 5811,683 cw(c5811,739) 5755,739 5755,882 cw(c5819.12,875.2) 5794.85,934.94 cw(c5815.15,874.65) 5875.44,894.93 ccw(c5916,917)
24V on L01 - TOP "L01_-_TOP_24V_P010" (solid, pour order 10): 6078,873 ccw(c6080.42,872.99) 6078.71,871.29 6080,870 6176,870 ccw(c6176,889.3) 6189.66,875.66 cw(c6254.04,818.86) 6319.13,874.84 cw(c6201.32,816.13) 6312.07,744.99 6196.01,744.99 cw(c6248.05,825.84) 6176,762.17 ccw(c6169.29,762.22) 6174,767 6079.41,767 ccw(c6083.35,763.36) 6078,763 cw(c6078.68,763.29) 6078,763.58 6078,718 ccw(c6086.49,716.02) 6079.1,711.39 ccw(c6194.2,706.54) 6085.64,668 6187.75,656.55 cw(c6187.85,656.38) 6187.86,656.58 ccw(c6191.51,665.33) 6193,655.96 6204.41,657 6371.58,657 ccw(c6371.58,757) 6442.29,686.29 6483.98,727.98 cw(c6512.98,699.01) 6513,740 6667.51,740 ccw(c6675.73,778.58) 6703.45,750.51 ccw(c6676.39,773.58) 6711.84,776.43 6711.84,971.34 ccw(c6639.22,966.14) 6685.25,1022.54 6644.94,1040.43 ccw(c6642.25,1034.35) 6642.17,1041 6494,1041 ccw(c6486.9,1041.06) 6491.88,1046.12 6482,1056 ccw(c6474.83,1048.94) 6474.76,1059 6421.42,1059 ccw(c6421.35,959.17) 6350.71,1029.71 6345.99,1024.99 cw(c6234.83,1156.74) 6220,985 6124,985 ccw(c6126.84,929.82) 6085.64,966.64 6078,959 6078,874
VBUS on L01 - TOP "L01_-_TOP_VBUS_P002" (solid, pour order 2): 7155,604 7091.25,672 6853.75,672 6802,589.2 6802,385 6778,361 4871,361 4590,642 1345,642 1211,776 1211,7610 1181,7640 856,7640 787,7571 787,537 978,346 1989,346 4216,346 4442,120 6627,120 7134,120 7155,141
GND on L08 - BOTTOM "L08_-_BOTTOM_GND_P046" (solid, pour order 46): 640.5,8369 1286.5,8369 4724,8369 4863.5,8229.5 4863.5,7204.5 4915,7153 8036.5,7153 8089,7100.5 8089,6055 8044.5,6010.5 7344,6010.5 6947.69,5614.19 6947.69,5013.81 6988,4973.5 8051.5,4973.5 8089,4936 8089,50 8063,24 608.95,24 591.5,45 591.5,153.5 591.5,7987.5 591.5,8308
GND_USB on L08 - BOTTOM "L08_-_BOTTOM_GND_USB_P036" (solid, remove dead copper, pour order 36): 8052,5985 7364.5,5985 6982,5602.5 6982,5024 7005,5001 8061,5001 8080,5020 8079,5021 8079,5958
EARTH_GND on L08 - BOTTOM "L08_-_BOTTOM_EARTH_GND_P030" (solid, pour order 30): 4995,8085 5067,8157 5939,8157 5985,8203 6346,8203 6392,8157 7347,8157 7405,8099 7405,7895 7394,7884 5030,7884 4995,7919
VBUS on L08 - BOTTOM "L08_-_BOTTOM_VBUS_P011" (solid, pour order 11): 7155,604 7091.25,672 6853.75,672 6802,589.2 6802,385 6778,361 4634,361 4353,642 1345,642 1211,776 1211,7610 1181,7640 856,7640 787,7571 787,531 972,346 1989,346 4216,346 4442,120 6627,120 7134,120 7155,141
1V8 on L05 - PWR "L05_-_PWR_1V8_P055" (solid, pour order 55): 4478.7,6725.2 4757.7,6725.2 4831.52,6799.02 7766.48,6799.02 7786.5,6779 7786.5,6045.5 7745,6004 7327.51,6004 6933,5609.49 6933,5006.5 6973.5,4966 8043,4966 8076,4933 8076,1312 8033.5,1269.5 6313.5,1269.5 6313.5,1268.5 6267.5,1222.5 6056.44,1222.5 6037,1241.94 6037,1500 6020.5,1516.5 5784.94,1516.5 5752.5,1548.94 5752.5,1699 5398.5,1699 5348,1648.5 5348,1374.5 5313.85,1340.35 4458.33,1340.35 4436.87,1361.81 4449,1373.95 4449,6702.5 4471.7,6725.2
NetC168_1 on L05 - PWR "L05_-_PWR_NETC168_1_P054" (solid, pour order 54): 5259,4944.25 5258.25,4944.25 5291.75,4944.25 5416.03,4819.97 5416.03,4724.03 5392,4700 5259,4700 5239.5,4719.5 5239.5,4933.75 5250,4944.25 5260.11,4944.25
3V3 on L05 - PWR "L05_-_PWR_3V3_P051" (solid, pour order 51): 4792.5,7965 4859,7898.5 4859,7201.5 4912,7148.5 7239.5,7148.5 7304,7084 7304,6840 7284,6820 4769.5,6820 4713.5,6764 4477,6764 4418,6705 4418,1352.5 4449,1321.5 5321,1321.5 5363.5,1364 5363.5,1635.5 5412.5,1684.5 5728.5,1684.5 5743,1670 5743,1532 5732.74,1521.74 5644.16,1521.74 5607.14,1484.72 5607.14,1035.36 5362.16,444.79 1367.5,440.5 1327,481 1327,7874 1327,7898.5 1327,7937 1349,7965
GND_USB on L05 - PWR "L05_-_PWR_GND_USB_P053" (solid, pour order 53): 8038.5,5980 7351,5980 6968.5,5597.5 6968.5,5019 6991.5,4996 8047.5,4996 8066.5,5015 8065.5,5016 8065.5,5953
VBUS on L05 - PWR "L05_-_PWR_VBUS_P039" (solid, pour order 39): 1190.5,7599.2 1209,7580.7 1209,7432.2 1186.5,7409.7 1032.99,7409.7 1020,7422.69 1020,7583.49 1035.71,7599.2
VBUS on L05 - PWR "L05_-_PWR_VBUS_P038" (solid, pour order 38): 1190.5,4349.6 1209,4331.1 1209,4182.6 1186.5,4160.1 1032.99,4160.1 1020,4173.09 1020,4333.89 1035.71,4349.6
VBUS on L05 - PWR "L05_-_PWR_VBUS_P037" (solid, pour order 37): 1190.5,1100 1209,1081.5 1209,933 1186.5,910.5 1032.99,910.5 1020,923.49 1020,1084.29 1035.71,1100
1V1 on L05 - PWR "L05_-_PWR_1V1_P034" (solid, pour order 34): 7342.11,6129.8 7456.36,6129.8 ccw(c7456.36,6150.29) 7470.85,6135.8 ccw(c7423.4,6183.25) 7490.5,6183.25 7490.5,6320.2 ccw(c7464.91,6320.2) 7483,6338.3 ccw(c7422.65,6277.96) 7422.64,6363.3 7332.33,6363.3 ccw(c7332.33,6306.97) 7292.5,6346.8 ccw(c7310.6,6328.7) 7285,6328.7 7285,6143.3 ccw(c7304.31,6143.3) 7290.5,6129.8
2V5 on L05 - PWR "L05_-_PWR_2V5_P033" (solid, pour order 33): 7357.34,6513 7471.6,6513 ccw(c7471.6,6533.48) 7486.08,6519 ccw(c7438.64,6566.44) 7505.74,6566.45 7505.74,6703.39 ccw(c7480.14,6703.4) 7498.24,6721.5 ccw(c7437.89,6661.16) 7437.88,6746.5 7347.57,6746.5 ccw(c7347.57,6690.17) 7307.74,6730 ccw(c7325.83,6711.89) 7300.24,6711.89 7300.24,6526.5 ccw(c7319.55,6526.5) 7305.74,6513
5V on L05 - PWR "L05_-_PWR_5V_P022" (solid, pour order 22): 5617,640 ccw(c5618.16,646.21) 5621.73,641 5831.58,641 ccw(c5831.58,741) 5902.29,670.29 5916,684 ccw(c5901.52,698.48) 5922,698.49 5922,747.27 ccw(c5891.29,747.28) 5913,769 ccw(c5879.21,735.22) 5879.2,783 5841,783 cw(c5841,785.41) 5839.29,783.71 5833,790 cw(c5835.41,792.41) 5832,792.41 5832,909 cw(c5859.02,909) 5839.92,928.11 5843.43,931.63 cw(c5846.75,928.3) 5846.75,933 5925,933 ccw(c5925,945.07) 5933.53,936.53 5941,944 ccw(c5938.59,946.41) 5942,946.41 5942,1343 cw(c5951.66,1343) 5944.83,1349.83 5946,1351 cw(c5955.65,1341.35) 5955.66,1355 6011,1355 ccw(c6011,1371.9) 6022.95,1359.95 6028,1365 ccw(c6020.76,1372.24) 6031,1372.24 6031,1465.03 ccw(c5990.05,1465.04) 6019,1494 ccw(c6011.77,1486.78) 6011.76,1497 5734,1497 ccw(c5734,1482.52) 5723.76,1492.76 5707,1476 ccw(c5764.93,1418.06) 5683,1418.06 5683,1087 cw(c5641.98,1086.99) 5670.98,1057.98 5655,1042 cw(c5604.31,1092.69) 5604.3,1021 ccw(c5580.45,908.89) 5518,1005 ccw(c5517.92,1002.76) 5516,1001.59 5516,752 ccw(c5669.31,743.26) 5554.75,641
24V on L05 - PWR "L05_-_PWR_24V_P013" (solid, pour order 13): 6322,950 cw(c6341,950) 6341,969 6585,969 cw(c6585,869) 6685,869 6685,760 cw(c6620,760) 6620,695 6339,695 cw(c6339,713) 6321,713
GND on L07 - GND "L07_-_GND_GND_P043" (solid, pour order 43): 640.5,8369 1286.5,8369 4724,8369 4863.5,8229.5 4863.5,7204.5 4915,7153 8036.5,7153 8089,7100.5 8089,6055 8044.5,6010.5 7344,6010.5 6947.69,5614.19 6947.69,5013.81 6988,4973.5 8051.5,4973.5 8089,4936 8089,50 8063,24 608.95,24 591.5,45 591.5,153.5 591.5,7987.5 591.5,8308
GND_USB on L07 - GND "L07_-_GND_GND_USB_P040" (solid, pour order 40): 8052,5985 7364.5,5985 6982,5602.5 6982,5024 7005,5001 8061,5001 8080,5020 8079,5021 8079,5958
EARTH_GND on L07 - GND "L07_-_GND_EARTH_GND_P029" (solid, pour order 29): 4995,8085 5069.5,8159.5 5941.5,8159.5 5985,8203 6346,8203 6389.5,8159.5 7344.5,8159.5 7405,8099 7405,7895 7394,7884 5030,7884 4995,7919
EARTH_GND on L04 - GND "L04_-_GND_EARTH_GND_P058" (solid, pour order 58): 4995,8085 5066,8156 5938,8156 5985,8203 6346,8203 6393,8156 7348,8156 7405,8099 7405,7895 7394,7884 5030,7884 4995,7919
GND on L04 - GND "L04_-_GND_GND_P044" (solid, pour order 44): 640.5,8369 1286.5,8369 4724,8369 4863.5,8229.5 4863.5,7204.5 4915,7153 8036.5,7153 8089,7100.5 8089,6055 8044.5,6010.5 7344,6010.5 6947.69,5614.19 6947.69,5013.81 6988,4973.5 8051.5,4973.5 8089,4936 8089,50 8063,24 608.95,24 591.5,45 591.5,153.5 591.5,7987.5 591.5,8308
GND_USB on L04 - GND "L04_-_GND_GND_USB_P041" (solid, pour order 41): 8052,5985 7364.5,5985 6982,5602.5 6982,5024 7005,5001 8061,5001 8080,5020 8079,5021 8079,5958
EARTH_GND on L02 - GND "L02_-_GND_EARTH_GND_P057" (solid, pour order 57): 4995,8085 5066,8156 5938,8156 5985,8203 6346,8203 6393,8156 7348,8156 7405,8099 7405,7895 7394,7884 5030,7884 4995,7919
GND on L02 - GND "L02_-_GND_GND_P045" (solid, pour order 45): 640.5,8369 1286.5,8369 4724,8369 4863.5,8229.5 4863.5,7204.5 4915,7153 8036.5,7153 8089,7100.5 8089,6055 8044.5,6010.5 7344,6010.5 6947.69,5614.19 6947.69,5013.81 6988,4973.5 8051.5,4973.5 8089,4936 8089,50 8063,24 608.95,24 591.5,45 591.5,153.5 591.5,7987.5 591.5,8308
GND_USB on L02 - GND "L02_-_GND_GND_USB_P042" (solid, pour order 42): 8052,5985 7364.5,5985 6982,5602.5 6982,5024 7005,5001 8061,5001 8080,5020 8079,5021 8079,5958

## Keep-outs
Keep-Out Layer:
  text ".Layer_Name" at 577,-558.49 h60

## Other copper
L01 - TOP:
  pour cut-out: 5891.41,787.87 6116.63,787.87 6116.63,760.24 5891.41,760.24
  pour cut-out: 5888.49,879.65 6113.71,879.65 6113.71,852.01 5888.49,852.01
  text ".Layer_Name" at 577,-558.49 h60
L08 - BOTTOM:
  text ".Layer_Name" at 581,-488.49 h60

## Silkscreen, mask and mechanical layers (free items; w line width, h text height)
Top Overlay:
  text "'.PRJ_Number'  .PCB_Rev" at 250,6248.5 h108.27 r90
  text "Bootmode8:11" at 5789,2972.5 h30
  text "Bootmode 4:7" at 6202.09,2970.52 h30
  text "Bootmode 0:3" at 6689,2970.5 h30
  text "Bootmode12：15" at 5355,2879.5 h30
  text "1V8" at 6407,1606 h40
  text "3V3" at 5196.5,1055.5 h40
  text "24V" at 6353.5,533.5 h40
  text "5V" at 5591.5,519 h40
  text "GND" at 7534.5,48.5 h40
  text "VBUS" at 6684.5,41.5 h40
  text ".Layer_Name" at 577,-558.49 h60
Bottom Overlay:
  text ".Layer_Name" at 581,-488.49 h60
Top Paste:
  text ".Layer_Name" at 577,-558.49 h60
Bottom Paste:
  text ".Layer_Name" at 581,-488.49 h60
Top Solder:
  lines w11.81: 0,1714.44 0,0 ; 0,0 0,8400 8100,8400 8100,0 0,0
  text ".Layer_Name" at 577,-558.49 h60
  text ".Layer_Name" at 577,-558.49 h60
Bottom Solder:
  lines w11.81: 0,1714.44 0,0 ; 0,0 8100,0 8100,8400 0,8400 0,0
  text ".Layer_Name" at 581,-488.49 h60
Drill Guide:
  text ".Layer_Name" at 577,-558.49 h60
M1 Board Outline:
  lines w11.81: 0,1714.44 0,0 ; 0,0 8100,0 8100,8400 0,8400 0,0
  text ".Layer_Name" at 577,-558.49 h60
M2 Board Dimensions:
  rectangle: 8656,-280 8781,-155
  rectangle: 8781,-405 9156,-280
  lines w7: 8656,-280 9656,-280 ; 8781,-405 8781,-155 ; 8906,-405 8906,-155 ; 9156,-405 9156,-155 ; 9406,-405 9406,-155 ; 8656,-405 9656,-405 9656,-155 8656,-155 8656,-405
  text ".Layer_Name" at 8376,5 h60
M3 3D STEP Top:
  text ".Layer_Name" at 577,-558.49 h60
M4 3D STEP Bottom:
  text ".Layer_Name" at 577,-558.49 h60
M5 Assembly Top:
  lines w10: -292,-630.17 6308,-630.17 ; -292,-426.83 6310,-426.83 ; -292,-223.5 -292,-833.5 3713,-833.5 6310,-833.5 6310,-223.5 -291.5,-223.5 -291.5,-833.5 1284,-833.5 ; 2173,-833.5 2173,-223.5 ; 3440,-426.83 3440,-223.5 ; 4280,-426.83 4280,-223.5 ; 4902,-840 4902,-637.17
  text "COMPONENTS MARKED 'DNP' SHOULD NOT BE POPULATED." at 1153.5,-18.5 h35
  text "ASSEMBLY VARIANT:" at 1153,-134 h35
  text ".VariantName" at 2189,-134 h35
  text "PCB VIEWED FROM TOP SIDE" at -228.5,-355.67 h60
  text "BOARD #:" at 2248,-355.67 h60
  text ".PRJ_Number" at 2793.5,-355.67 h60
  text "REV:" at 3638,-355.67 h60
  text ".PCB_Rev" at 3929.5,-355.67 h60
  text "SVN REV:" at 4476,-355.67 h60
  text ".VersionControl_RevNumber" at 4982,-355.67 h60
  text "TID #:" at 2248,-559 h60
  text ".TID" at 2793.5,-559 h60
  text "PLOT NAME =" at -228.5,-764.34 h60
  text ".plot_File_Name" at 577,-764.34 h60
  text "GENERATED    :" at 2250,-764.34 h60
  text ".Print_Date" at 3119.5,-764.34 h60
  text ".Print_Time" at 3848.5,-764.34 h60
  text "TEXAS INSTRUMENTS" at 5113,-764.34 h60
M6 Assembly Bottom:
  lines w10: -292.5,-427.33 6309.5,-427.33 ; -290.5,-630.67 6309.5,-630.67 ; 1115.5,-840.5 1115.5,-637.67 ; 1737.5,-427.33 1737.5,-224 ; 2577.5,-427.33 2577.5,-224 ; 3844.5,-834 3844.5,-224 ; 4733.5,-834 6309,-834 6309,-224 -292.5,-224 -292.5,-834 2304.5,-834 6309.5,-834 6309.5,-224
  text "COMPONENTS MARKED 'DNP' SHOULD NOT BE POPULATED." at 6102,-18 h35
  text ".VariantName" at 5058,-134 h35
  text "ASSEMBLY VARIANT:" at 6097,-134 h35
  text ".VersionControl_RevNumber" at 1035.5,-356.17 h60
  text "SVN REV:" at 1541.5,-356.17 h60
  text ".PCB_Rev" at 2088,-356.17 h60
  text "REV:" at 2379.5,-356.17 h60
  text ".PRJ_Number" at 3224,-356.17 h60
  text "BOARD #:" at 3769.5,-356.17 h60
  text "PCB VIEWED FROM BOTTOM SIDE" at 6246,-356.17 h60
  text ".TID" at 3224,-559.5 h60
  text "TID #:" at 3769.5,-559.5 h60
  text "TEXAS INSTRUMENTS" at 904.5,-764.84 h60
  text ".Print_Time" at 2169,-764.84 h60
  text ".Print_Date" at 2898,-764.84 h60
  text "GENERATED    :" at 3767.5,-764.84 h60
  text ".plot_File_Name" at 5440.5,-764.84 h60
  text "PLOT NAME =" at 6246,-764.84 h60
M9 Title Sheet:
  drawing of 57 lines, arcs and shapes, not listed
  text "1" at 739.84,8336.5 h70
  text "2" at 3235.5,8336.5 h70
  text "3" at 5724.84,8336.5 h70
  text "4" at 8231.51,8336.5 h70
  text "5" at 10730.5,8336.5 h70
  text "6" at 13235.5,8336.5 h70
  text "A" at -416.5,7193.5 h70
  text "A" at 14383.5,7193.5 h70
  text "B" at -416.5,4813.5 h70
  text "B" at 14383.5,4813.5 h70
  text "C" at -416.5,2438.5 h70
  text "C" at 14383.5,2438.5 h70
  text "PROJECT TITLE:" at 11343.5,577.5 h45
  text ".PRJ_Title" at 11393.5,444.17 h70
  text "DESIGNED FOR:" at 11343.5,276.5 h45
  text ".PRJ_Customer" at 11393.5,136.5 h70
  text "D" at -416.5,68.5 h70
  text "D" at 14383.5,68.5 h70
  text "FILE NAME:" at 11343.5,-23.5 h45
  text ".PCB_File_Name_No_Path" at 11393.5,-143.5 h70
  text "Texas Instruments (TI) and/or its licensors do not warrant the accuracy or completeness of this specification" at 6374,-305.34 h45
  text "ENGINEER:" at 11343.5,-313.5 h45
  text "LAYOUT BY:" at 12848.5,-313.5 h45
  text "or any information contained therein. TI and/or its licensors do not warrant that this design will meet" at 6329.01,-418 h45
  text ".PRJ_Engineer" at 11393.5,-468.49 h70
  text ".PCB_Layout" at 12899,-468.49 h70
  text "the specifications, will be suitable for your application or fit for any particular purpose, or will operate in" at 6329.01,-530.67 h45
  text ".Layer_Name" at 577,-558.49 h60
  text "ALTIUM DESIGNER VERSION:" at 12848.5,-623.5 h45
  text "an implementation. TI and/or its licensors do not warrant that the design is production worthy. You should" at 6329.01,-643.33 h45
  text "completely validate and test your design implementation to confirm the system functionality for your application." at 6374,-756 h45
  text ".print_Scale" at 11393.5,-756.83 h70
  text ".Application_BuildNumber" at 12899,-756.83 h70
  text "1" at 739.84,-963.5 h70
  text "2" at 3235.5,-963.5 h70
  text "3" at 5724.84,-963.5 h70
  text "4" at 8231.51,-963.5 h70
  text "5" at 10730.5,-963.5 h70
  text "6" at 13235.5,-963.5 h70
M10 Fab Notes:
  drawing of 189 lines, arcs and shapes, not listed
  text "DESIGN INFORMATION" at 12382.02,6656.17 h60
  text "MIN. TRACK WIDTH:" at 11737.46,6524.05 h60
  text "4" at 12833.7,6524.05 h60
  text "MIL" at 12988.46,6524.05 h60
  text "0,15" at 12696.85,6402.36 h60
  text "MIN. CLEARANCE:" at 11737.46,6399.92 h60
  text "mm" at 12988.46,6399.92 h60
  text "MIN. VIA PAD SIZE:" at 11737.46,6275.8 h60
  text "19" at 12803.71,6275.8 h60
  text "MIL" at 12988.46,6275.8 h60
  text "0.05mm (2MIL)" at 12432.46,6145.9 h60
  text "MINIMUM ANNULAR RING" at 11408.23,6137.67 h60
  text "EXTERNAL" at 13140.46,6137.67 h60
  text "PER" at 11608.23,6027.55 h60
  text "IPC-D-275 CLASS 2 LEVEL C" at 11828.23,6027.54 h60
  text "MIL, HOLES" at 13316.46,5927.07 h60
  text "+/-" at 12924,5918.48 h60
  text "+/-" at 13778,5918.48 h60
  text "REGISTRATION TOLERANCES:" at 11408.23,5917.42 h60
  text "METAL" at 12608,5917.42 h60
  text "5" at 13184.2,5917.42 h60
  text "3" at 14017.2,5917.42 h60
  text "MIL" at 14133.46,5917.42 h60
  text "HOLE SIZE TOLERANCE (UNLESS OTHERWISE SPECIFIED):" at 11408.23,5819.1 h60
  text "+/-" at 13778,5816.23 h60
  text "3" at 14017.2,5815.17 h60
  text "MIL" at 14133.46,5815.17 h60
  text "MATERIAL:" at 11333.46,5677.52 h60
  text "FR-4 High Tg" at 12319.9,5549 h60
  text "X" at 12175.46,5541.01 h60
  text "FR-408" at 11754.46,5536.49 h60
  text "OTHER" at 13242.46,5536.49 h60
  text "62 MIL (1.6mm) +/-10%" at 12074.56,5393.46 h60
  text "X" at 11954.46,5391.01 h60
  text "THICKNESS:" at 11408.23,5385.24 h60
  text "OTHER" at 13359.46,5385.24 h60
  text "TOLERANCE:" at 11408.23,5246.92 h60
  text "X" at 12256.46,5246.92 h60
  text "ANSI IPC-6012 TYPE 3 CLASS 2" at 12434.48,5246.92 h60
  text "OTHER +/-" at 12434.46,5102.73 h60
  text "BOW & TWIST:" at 11408.23,4957.54 h60
  text "X" at 12256.46,4957.54 h60
  text "ANSI IPC-6012 TYPE 3 CLASS 2" at 12434.48,4957.54 h60
  text "OTHER +/-" at 12434.46,4810.85 h60
  text "DRILLING:" at 11333.46,4680.23 h60
  text "NC_DRILL FILES" at 13094.46,4575.04 h60
  text "REFERENCE:" at 11408.23,4571.1 h60
  text "X" at 12065.46,4571.01 h60
  text "AS SHOWN" at 12243.46,4571.1 h60
  text "X" at 12966.46,4571.1 h60
  text "OTHER" at 13392.46,4428.85 h60
  text "PTH COPPER THICKNESS:" at 11407.91,4425.32 h60
  text "X" at 12547.14,4425.32 h60
  text "20-30 um" at 12675.14,4425.32 h60
  text "BOARD FINISH:" at 11333.46,4277.73 h60
  text "SILKSCREEN:" at 11488.68,4167.6 h60
  text "X" at 12446.46,4167.6 h60
  text "TOP" at 12563.46,4167.6 h60
  text "X" at 12956.46,4167.6 h60
  text "BOTTOM" at 13074.46,4167.6 h60
  text "SILKSCREEN COLOR:" at 11488.68,4012.41 h60
  text "X" at 12445.46,4012.41 h60
  text "WHITE" at 12563.46,4012.41 h60
  text "OTHER" at 13074.46,4012.41 h60
  text "X" at 12576.46,3868.96 h60
  text "GREEN" at 12694.46,3868.96 h60
  text "OTHER" at 13312.46,3868.96 h60
  text "SOLDER RESIST COLOR:" at 11488.68,3862.1 h60
  text "X" at 12576.46,3714.71 h60
  text "MATTE" at 12694.46,3714.71 h60
  text "SEMI-GLOSS" at 13312,3714.07 h60
  text "IMMERSION GOLD (ENIG)" at 12394.46,3541.94 h60
  text "ENEPIG" at 13732,3534.72 h60
  text "SURFACE FINISH:" at 11333.46,3533.72 h60
  text "X" at 12216.46,3533.72 h60
  text "IMM. TIN/SILVER OR EQUIV" at 11663,3396.4 h60
  text "OTHER" at 13094.46,3392.47 h60
  text "ARRAY/PANEL:" at 11333.46,3237.09 h60
  text "CUT AND TRIM PER M1 BOARD OUTLINE" at 12394.46,3228.87 h60
  text "N.C. ROUTE" at 12394.46,3092.9 h60
  text "X" at 13082.46,3092.9 h60
  text "V. SCORE" at 13260.46,3092.9 h60
  text "CERTIFICATION:" at 11333.46,2963.77 h60
  text "MATERIALS AND WORKMANSHIP FOR ALL PCBS" at 12058.46,2963.77 h60
  text "TO MEET OR EXCEED THE REQUIREMENTS OF:" at 12058.46,2869.71 h60
  text "X" at 11695.97,2741.08 h60
  text "ANSI IPC-A-600F CLASS ->" at 11823.96,2741.08 h60
  text "X" at 13471.97,2741.08 h60
  text "2" at 13581.96,2741.08 h60
  text "1" at 13266.96,2739.58 h60
  text "3" at 13935.96,2739.58 h60
  text "X" at 12507.97,2593.39 h60
  text "RoHS" at 12635.96,2593.39 h60
  text "OTHER" at 13280.36,2593.39 h60
  text "PER ORDER" at 13677.42,2593.39 h60
  text "ALL BOARDS MUST MEET OR EXCEED UL94-V0 REQUIREMENTS." at 11361,2439.57 h60
  text "PCB MUST BEAR THE UL94V-0 UL REGISTERED MATERIAL ID NUMBER" at 11361,2323.5 h60
  text "ADDITIONAL REQUIREMENTS:" at 11333.46,2154.08 h60
  text "MICROSECTION:" at 11408.23,2046.95 h60
  text "YES" at 12313.96,2046.95 h60
  text "REQUIRED" at 13175.46,1902.62 h60
  text "BARE BOARD ELEC. TEST:" at 11408.23,1899.76 h60
  text "NONE" at 12713.96,1899.76 h60
  text "X" at 13057.46,1899.76 h60
  text "PER ORDER" at 13767.46,1899.76 h60
  text "XX MIL VIAS REQUIRE NON-CONDUCTIVE FILL AND PLANARIZE" at 11576.38,1694.82 h59
  text "XX MIL VIAS REQUIRE CONDUCTIVE FILL AND PLANARIZE" at 11584.38,1590.84 h60
  text "OUTER XX MIL TRACES REQUIRE 50 OHM SINGLE-ENDED IMPEDANCE" at 11583.39,1427.46 h58
  text "LAYER 2 & 3 (INNER LAYERS) XX MIL WIDE, XX MIL SPACE / TRACES REQUIRE 100 OHM DIFFERENTIAL IMPEDANCE" at 11575.39,1191.74 h60
  text ".Layer_Name" at 577,-558.49 h60
M11 Gerber Information:
  lines w10: -292,-630.17 6308,-630.17 ; -292,-426.83 6310,-426.83 ; -292,-223.5 -292,-833.5 3713,-833.5 6310,-833.5 6310,-223.5 -291.5,-223.5 -291.5,-833.5 1284,-833.5 ; 2173,-833.5 2173,-223.5 ; 3440,-426.83 3440,-223.5 ; 4280,-426.83 4280,-223.5 ; 4902,-840 4902,-637.17
  text "ALL ARTWORK VIEWED FROM TOP SIDE" at -228.5,-355.67 h60
  text "BOARD #:" at 2248,-355.67 h60
  text ".PRJ_Number" at 2793.5,-355.67 h60
  text "REV:" at 3638,-355.67 h60
  text ".PCB_Rev" at 3929.5,-355.67 h60
  text "SVN REV:" at 4476,-355.67 h60
  text ".VersionControl_RevNumber" at 4982,-355.67 h60
  text "LAYER NAME =" at -228.5,-558.49 h60
  text "TID #:" at 2248,-559 h60
  text ".TID" at 2793.5,-559 h60
  text "PLOT NAME =" at -228.5,-764.34 h60
  text ".plot_File_Name" at 577,-764.34 h60
  text "GENERATED    :" at 2250,-764.34 h60
  text ".Print_Date" at 3119.5,-764.34 h60
  text ".Print_Time" at 3848.5,-764.34 h60
  text "TEXAS INSTRUMENTS" at 5113,-764.34 h60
